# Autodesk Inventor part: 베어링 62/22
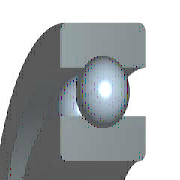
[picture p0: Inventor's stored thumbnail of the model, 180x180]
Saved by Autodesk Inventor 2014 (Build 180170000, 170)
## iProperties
Created: 2009-02
Part Number: 베어링 62/22
Material: 강, 연강
Description: 깊은 그루브 볼 베어링
Document SubType Name: Modeling
Standard: KS B 2023
Designer: KYOUNG IL JANG
Standards Organization: KS
Language: ko-KR
Size Designation: 62/22 - 22 x 50 x 14
Categories: <MemberInstance><Categories><Category DisplayName="샤프트 부품" InternalName="7f7aeb1f-a693-4053-b835-cee3144e0d98" Mnemonic="SHFT"><Category DisplayName="베어링" Inter
Density: 7.86 g/cm^3
Mass: 107.995 g
Surface Area: 96.9171 cm^2
Volume: 13.7399 cm^3
Appearance: 강철
IsCustomPart: 0
Author: KYOUNG IL JANG
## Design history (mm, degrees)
sketch "스케치" dims "d0" = 7.28 (= -0.26 x WD + 0.26 x BD)
  geometry: L1 (3.36, 18)-(10.64, 18); L2 (7, 18)-(7, 14.36); L3 (7, 18)-(7, 21.64); L4 (4.295, 15.564)-(0, 15.564); L5 (0, 11)-(14, 11); L6 (4.295, 20.436)-(0, 20.436); L7 (0, 25)-(14, 25); L8 (14, 11)-(14, 15.564); L9 (9.705, 15.564)-(14, 15.564); L10 (9.705, 20.436)-(14, 20.436); L11 (14, 25)-(14, 20.436); L12 (-1.4, 0)-(8.4, 0) reference; L13 (0, -0.3)-(0, 5.3) reference
  constraints: 22 end point, 4 point on line, 2 collinear, 2 perpendicular, 2 symmetric about line, 1 midpoint, 1 parallel, 14 other
  dimensions: "d9" = 22 diameter of L5 L12 (= WD); "d11" = 50 diameter of L7 L12 (= BD); "d12" = 14 distance between parallel lines of L8 L13 (= KB); "d13" = 31.128 diameter of L9 L12 (= 0.326 x BD + 0.674 x WD)
revolve "본체" stored, may be unused: angle "d6" = 90 deg
revolve "볼" stored, may be unused: angle "d7" = 90 deg
pattern_circular "IDS_ARRAYBALL[SIMPL:T]" dims angle "d3" = 360 deg
body "Solid1"
fillet "모깎기1" dims "d1" = 1 (= KRS)
other parameters: "WD" = 22 [user parameter; used in 5 equation terms], "BD" = 50 [user parameter; used in 5 equation terms], "KB" = 14 [user parameter; used in 1 equation term], "KRS" = 1 [user parameter; used in 1 equation term], "d4" = 0, "d5" = 0, "d8" = 0, "d14" = 0, "d15" = 0, "BBA" = 0 [user parameter], "BC0" = 7154000 [user parameter], "BC" = 1.2233e+07 [user parameter], "BR" = 25 (= 0.5 x BD) [user parameter], "WR" = 11 (= 0.5 x WD) [user parameter]
